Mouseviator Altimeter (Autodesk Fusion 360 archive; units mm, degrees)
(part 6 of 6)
sketch "Panel Sketch" plane through (0, -8.25, 0) normal (0, -1, 0) x axis (1, 0, 0)
  line L1 (-40.1846, 22.0238) -> (-35.5682, 33.812)
  line L2 (-40.4655, -20.5361) -> (-40.4655, 20.5361)
  line L3 (-35.5682, -33.812) -> (-40.1846, -22.0238)
  line L4 (-22.8502, -40.1861) -> (-33.2529, -36.1249)
  line L5 (21.3665, -40.4655) -> (-21.3665, -40.4655)
  line L6 (33.2529, -36.1249) -> (22.8502, -40.1861)
  line L7 (40.1846, -22.0238) -> (35.5682, -33.812)
  line L8 (40.4655, 20.5361) -> (40.4655, -20.5361)
  line L9 (35.5682, 33.812) -> (40.1846, 22.0238)
  line L10 (-24.1331, 40.4655) -> (24.1231, 40.4655)
  line L11 (26.0523, 39.9806) -> (33.1998, 36.1452)
  line L12 (-33.685, 35.9265) -> (-26.049, 39.9877)
  circle C1 centre (31.4309, 31.4309) radius 2.159
  circle C2 centre (-31.4309, -31.4309) radius 2.159
  circle C3 centre (-31.4309, 31.4309) radius 2.159
  circle C4 centre (31.4309, -31.4309) radius 2.159
  circle C5 centre (0, 0) radius 39.6875
  arc A1 centre (-36.3855, 20.5361) radius 4.08 clockwise from (-40.4655, 20.5361) to (-40.1846, 22.0238)
  arc A2 centre (-36.3855, -20.5361) radius 4.08 clockwise from (-40.1846, -22.0238) to (-40.4655, -20.5361)
  arc A3 centre (-31.7692, -32.3242) radius 4.08 clockwise from (-33.2529, -36.1249) to (-35.5682, -33.812)
  arc A4 centre (-21.3665, -36.3855) radius 4.08 clockwise from (-21.3665, -40.4655) to (-22.8502, -40.1861)
  arc A5 centre (21.3665, -36.3855) radius 4.08 clockwise from (22.8502, -40.1861) to (21.3665, -40.4655)
  arc A6 centre (31.7692, -32.3242) radius 4.08 clockwise from (35.5682, -33.812) to (33.2529, -36.1249)
  arc A7 centre (36.3855, -20.5361) radius 4.08 clockwise from (40.4655, -20.5361) to (40.1846, -22.0238)
  arc A8 centre (36.3855, 20.5361) radius 4.08 clockwise from (40.1846, 22.0238) to (40.4655, 20.5361)
  arc A9 centre (31.7692, 32.3242) radius 4.08 clockwise from (33.1998, 36.1452) to (35.5682, 33.812)
  arc A10 centre (-31.7692, 32.3242) radius 4.08 clockwise from (-35.5682, 33.812) to (-33.685, 35.9265)
  arc A11 centre (24.1231, 36.3855) radius 4.08 clockwise from (24.1231, 40.4655) to (26.0523, 39.9806)
  arc A12 centre (-24.1331, 36.3855) radius 4.08 clockwise from (-26.049, 39.9877) to (-24.1331, 40.4655)
sketch "Clamping Holes" plane through (0, -8.25, 0) normal (0, -1, 0) x axis (1, 0, 0)
  line L1 (0, 17.2297) -> (0, 0)
  line L2 (-22.2137, 0) -> (0, 0)
  circle C1 centre (-36.96, 18.76) radius 1
  circle C2 centre (36.96, 18.76) radius 1
  circle C3 centre (-36.96, -18.76) radius 1
  circle C4 centre (36.96, -18.76) radius 1
  circle C5 centre (-18.76, 36.96) radius 1
  circle C6 centre (18.76, 36.96) radius 1
  circle C7 centre (18.76, -36.96) radius 1
  circle C8 centre (-18.76, -36.96) radius 1
  point P1 (0, 0)
  point P3 (0, 0)
  point P5 (0, 0)
  point P2 (-36.96, 18.76)
  point P10 (-18.76, 36.96)
  coincident P1 P3
  vertical L1
  coincident P1 P5
  perpendicular L1 L2
  symmetric C1 L1 C2
  symmetric C1 L2 C3
  symmetric L2 C2 C4
  symmetric L1 C5 C6
  symmetric L2 C5 C8
  symmetric L2 C6 C7
  dimension "d32" diameter C1 = 2
  dimension "d33" distance P1 P2 = 18.76 (= "( 37.52 / 2 ) * 1 mm")
  dimension "d34" distance P1 P2 = 36.96 (= "( 73.92 / 2 ) * 1 mm")
  dimension "d37" diameter C5 = 2 (= "d32")
  dimension "d38" distance P1 P10 = 36.96 (= "d34")
  dimension "d39" distance P1 P10 = 18.76 (= "d33")
hole "Hole1" HoleDepth 10.25 HoleDiameter 2.8 CBDepth 2.5 CBDiameter 5
component_from_bodies "Body->Comp"
sketch "Top Sketch" plane through (0, 0, 41.4655) normal (0, 0, 1) x axis (-1, 0, 0)
  line L1 (-24.1231, 7.25) -> (24.1331, 7.25)
  line L2 (24.1331, -2) -> (-24.1231, -2)
  line L3 (-22.19, 6.25) -> (22.19, 6.25)
  line L4 (22.19, 0.25) -> (-22.19, 0.25)
  line L5 (-22.19, 3.25) -> (22.19, 3.25)
  line L6 (-24.1231, 8.25) -> (24.1331, 8.25)
  line L7 (-24.1231, -2) -> (-24.1231, 7.25)
  line L8 (24.1331, 7.25) -> (24.1331, -2)
  line L9 (22.19, 0.1) -> (-22.19, 0.1)
  line L10 (-22.19, 6.4) -> (22.19, 6.4)
  line L11 (-15.15, 0.1) -> (15.15, 0.1)
  line L12 (-15.15, 6.4) -> (-15.15, 0.1)
  line L13 (15.15, 6.4) -> (-15.15, 6.4)
  line L14 (15.15, 0.1) -> (15.15, 6.4)
  line L15 (-15.15, 6.4) -> (15.15, 0.1)
  line L16 (15.15, 6.4) -> (-15.15, 0.1)
  arc A1 centre (-22.19, 3.25) radius 3 clockwise from (-22.19, 0.25) to (-22.19, 6.25)
  arc A2 centre (22.19, 3.25) radius 3 clockwise from (22.19, 6.25) to (22.19, 0.25)
  arc A3 centre (22.19, 3.25) radius 3.15 clockwise from (22.19, 6.4) to (22.19, 0.1)
  arc A4 centre (-22.19, 3.25) radius 3.15 clockwise from (-22.19, 0.1) to (-22.19, 6.4)
  point P12 (0, 3.25)
  point P1 (0, 0)
  point P21 (15.15, 0.1)
  point P25 (0, 3.25)
  point P11 (-22.19, 3.25)
  point P10 (22.19, 3.25)
  point P23 (-15.15, 6.4)
  point P24 (15.15, 6.4)
  tangent L3 A1
  tangent A1 L4
  parallel L3 L4
  tangent L4 A2
  tangent L3 A2
  horizontal L5
  midpoint L5 P12
  vertical P1 P12
  horizontal L11
  perpendicular L11 L12
  parallel L11 L13
  parallel L12 L14
  coincident L9 P21
  coincident L15 P25
  coincident L16 P25
  coincident P12 P25
  dimension "d54" diameter A1 = 6
  dimension "d56" distance P11 L6 = 5
  dimension "d57" distance P10 P11 = 44.38
  dimension "d60" = 0.15
  dimension "d70" distance P23 P24 = 30.3
extrude "Extrude2" cut sketch "Top Sketch" profile of L3 A1 L4 A2 L9 L10 A3 A4 against normal blind 1.7
extrude "Extrude2" cut sketch "Top Sketch" profile of L3 L4 L9 L10 L11 L12 L13 L14 to an object
work_plane "WorkPlane1"
sketch "LED Angle" plane through (0, -3.25, 41.4655) normal (0, -1, 0) x axis (1, 0, 0)
  line L1 (14.8802, -5) -> (-0.0147, -1.0089)
  line L2 (50, -10.3752) -> (0, -10.3752)
  line L3 (0, 22.6624) -> (0, -10.6292)
  line L4 (-14.8802, -5) -> (-0.0147, -1.0089)
  line L5 (-24.1331, 0) -> (24.1231, 0)
  point P1 (0, 0)
  point P2 (0, -10.6292)
  point P3 (14.8802, -5)
  point P8 (-14.8802, -5)
  horizontal L2
  vertical P1 P2
  perpendicular L2 L3
  symmetric P3 L3 P8
  dimension "d104" angle L1 L2 = 15 (= "Angular Dimension-2")
  dimension "d106" distance P3 L5 = 5
pipe "Pipe2" SectionSize 6.5 SectionThickness 1.375
component_insert "Component Insert"
joint "Assemble1" alignOffsetX 0 alignOffsetY 0 alignOffsetZ -3
copy_paste "CutPaste"
work_plane "WorkPlane1"
mirror_component "MirrorComponent1"
derived_instance "DerivedInstance1"
mirror "Mirror1" mirrorStitchTolerance 0.1
extrude "Extrude1" new body sketch "Top Sketch" profile of L3 A1 L4 A2 L12 L14 against normal blind 1.7 bodies "Top LED Holder"
sketch "Top Sketch" plane through (0, 0, 41.4655) normal (0, 0, 1) x axis (-1, 0, 0)
  line L1 (-22.19, 6.25) -> (22.19, 6.25)
  line L2 (22.19, 0.25) -> (-22.19, 0.25)
  line L3 (0, 6.25) -> (0, 0.25)
  line L4 (-12.5, 6.225) -> (12.5, 6.225)
  line L5 (12.5, 0.275) -> (-12.5, 0.275)
  line L6 (-12.5, 3.25) -> (12.5, 3.25)
  line L7 (-13.6, 7.15) -> (13.6, 7.15)
  line L8 (13.6, -0.65) -> (-13.6, -0.65)
  line L9 (-13.6, 3.25) -> (13.6, 3.25)
  arc A1 centre (22.19, 3.25) radius 3 clockwise from (22.19, 6.25) to (22.19, 0.25)
  arc A2 centre (-22.19, 3.25) radius 3 clockwise from (-22.19, 0.25) to (-22.19, 6.25)
  arc A3 centre (-12.5, 3.25) radius 2.975 clockwise from (-12.5, 0.275) to (-12.5, 6.225)
  arc A4 centre (12.5, 3.25) radius 2.975 clockwise from (12.5, 6.225) to (12.5, 0.275)
  arc A5 centre (-13.6, 3.25) radius 3.9 clockwise from (-13.6, -0.65) to (-13.6, 7.15)
  arc A6 centre (13.6, 3.25) radius 3.9 clockwise from (13.6, 7.15) to (13.6, -0.65)
  circle C1 centre (-15.475, 3.25) radius 2.5
  circle C2 centre (15.475, 3.25) radius 2.5
  circle C3 centre (16.5801, 3.25) radius 1.5
  point P8 (0, 0.25)
  point P9 (0, 6.25)
  point P16 (0, 3.25)
  point P22 (-13.6, 3.25)
  point P23 (0, 3.25)
  point P24 (-15.475, 3.25)
  point P25 (15.475, 3.25)
  point P26 (16.5801, 3.25)
  midpoint L2 P8
  midpoint L1 P9
  tangent L4 A3
  tangent A3 L5
  parallel L4 L5
  tangent L5 A4
  tangent L4 A4
  perpendicular L3 L6
  midpoint L3 P16
  midpoint L6 P16
  tangent L7 A5
  tangent A5 L8
  parallel L7 L8
  tangent L8 A6
  tangent L7 A6
  coincident L6 P22
  parallel L6 L9
  coincident P16 P23
  midpoint L9 P23
  midpoint A3 P24
  midpoint A4 P25
  horizontal P23 P26
  dimension "d115" distance L4 L5 = 5.95
  dimension "d116" = 30.95
  dimension "d117" distance L7 L8 = 7.8
  dimension "d118" = 35
  dimension "d123" diameter C2 = 5
  dimension "d124" diameter C1 = 5 (= "d123")
  dimension "d126" diameter C3 = 3
extrude "Extrude2" add sketch "Top Sketch" profile of L4 A3 L5 A4 C1 C2 C3 along normal blind 2
extrude "Extrude3" add sketch "Top Sketch" profile of L1 L2 L4 A3 L5 A4 L7 A5 L8 A6 C1 C2 along normal blind 1
chamfer "Chamfer1" distance 0.8
extrude "Extrude4" cut sketch "Top Sketch" profile of A4 A6 C2 C3 to an object
sketch "Bottom Sketch" plane through (0, 0, 39.7655) normal (0, 0, -1) x axis (1, 0, 0)
  line L1 (22.19, 0.25) -> (-22.19, 0.25)
  line L2 (-22.19, 6.25) -> (22.19, 6.25)
  line L3 (9, 0.25) -> (-9, 0.25)
  line L4 (-9, 6.25) -> (9, 6.25)
  line L5 (9, 3.25) -> (-9, 3.25)
  line L6 (-11.5981, 4.75) -> (-16.5801, 4.75)
  line L7 (-11.5981, 1.75) -> (-11.5981, 4.75)
  line L8 (-16.5801, 1.75) -> (-11.5981, 1.75)
  line L9 (-16.5801, 4.75) -> (-16.5801, 1.75)
  circle C1 centre (-16.5801, 3.25) radius 1.5
  arc A1 centre (-22.19, 3.25) radius 3 clockwise from (-22.19, 0.25) to (-22.19, 6.25)
  arc A2 centre (22.19, 3.25) radius 3 clockwise from (22.19, 6.25) to (22.19, 0.25)
  circle C2 centre (-16.5801, 3.25) radius 1
  arc A3 centre (9, 3.25) radius 3 clockwise from (9, 6.25) to (9, 0.25)
  arc A4 centre (-9, 3.25) radius 3 clockwise from (-9, 0.25) to (-9, 6.25)
  point P16 (0, 3.25)
  point P19 (-11.5981, 1.75)
  point P17 (-16.5801, 4.75)
  point P20 (-16.5801, 1.75)
  point P9 (-16.5801, 3.25)
  point P1 (0, 0)
  point P15 (9, 3.25)
  concentric C1 C2
  tangent L3 A3
  tangent A3 L4
  parallel L3 L4
  tangent L4 A4
  tangent L3 A4
  parallel L1 L5
  midpoint L5 P16
  horizontal L6
  vertical L7
  horizontal L8
  vertical L9
  coincident A4 P19
  coincident C1 P17
  coincident C1 P20
  vertical P9 P20
  vertical P1 P16
  horizontal P9 P16
  dimension "d129" diameter A3 = 6
  dimension "d130" distance P15 P16 = 9
extrude "Extrude5" cut sketch "Bottom Sketch" profile of C1 L1 L2 L3 A3 L4 A4 L6 L7 L8 against normal blind 1
extrude "Extrude6" cut sketch "Bottom Sketch" profile of L1 L2 L3 A3 L4 A4 L7 against normal blind 2.5
work_plane "WorkPlane1"
hole "Hole1" HoleDepth 7 HoleDiameter 3.2 CSDiameter 6.3
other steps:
derived_base_feature "Derived Base Feature"
pipe "Pipe2" SectionSize 6.5 SectionThickness 1.375
mirror "Mirror1" mirrorStitchTolerance 0.1
base_feature "Base Feature" bodies "Standard Bezel"
extrude "Extrude1" cut sketch "Top Sketch" profile of L3 A1 L4 A2 L9 L10 A3 A4 against normal blind 1.7
pipe "Pipe2" SectionSize 6.5 SectionThickness 1.375
mirror "Mirror1" mirrorStitchTolerance 0.1
hole "Hole1" HoleDepth 7 HoleDiameter 3.2 CSDiameter 6.3
create_component "CreateComponent1"
create_component "CreateComponent2"
create_component "CreateComponent4"
remove_body "RemoveBody1"
extrude "Extrude2" cut sketch "Top Sketch" profile of L3 A1 L4 A2 L9 L10 A3 A4 against normal blind 1.7
joint_origin "JointOrigin1"
create_component "CreateComponent5"
remove_instance "RemoveInstance1"
create_component "CreateComponent1"
create_component "CreateComponent6"
named bodies: "Standard Bezel", "Seal", "Top LED Holder"

design "Bezel VSI & ALT MS33549B" references "Bezel LED and Glass MS33638C"
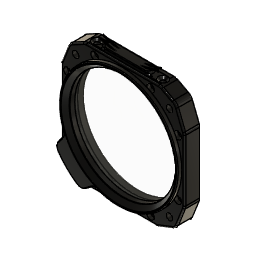
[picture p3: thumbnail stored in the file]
external_derived "ExternalDerived1" bodies "Standard Bezel"
external_derived "Top Sketch" bodies "Body1", "Body2", "Top LED Holder"
derived_instance "DerivedInstance3"
derived_instance "DerivedInstance4"
derived_instance "DerivedInstance1"
derived_instance "DerivedInstance2"
canvas "Canvas2"
sketch "Front Face" plane through (0, 2, 0) normal (0, 1, 0) x axis (-1, 0, 0)
  line L1 (28.9018, -41.4655) -> (21.3689, -41.4655)
  line L2 (41.4655, -20.5361) -> (41.4655, -28.9018)
  line L3 (31.4309, -31.4309) -> (0, 0)
  line L4 (1.8865, 0) -> (0, 0)
  line L5 (27.7621, 0) -> (1.8865, 0)
  line L6 (1.5, -41.4655) -> (1.5, -39.6216)
  line L7 (21.3665, -41.4655) -> (1.5, -41.4655)
  line L8 (33.6166, -37.0564) -> (23.2139, -41.1177)
  line L9 (41.1157, -22.3885) -> (36.4994, -34.1766)
  line L10 (41.4655, 20.5361) -> (41.4655, -20.5361)
  line L11 (36.4994, 34.1766) -> (41.1157, 22.3885)
  line L12 (26.5185, 40.8706) -> (34.1546, 36.8093)
  line L13 (-24.1231, 41.4655) -> (24.1331, 41.4655)
  line L14 (-33.6166, 37.0564) -> (-26.5251, 40.8618)
  line L15 (-41.1157, 22.3885) -> (-36.4994, 34.1766)
  line L16 (-41.4655, -20.5361) -> (-41.4655, 20.5361)
  line L17 (-36.4994, -34.1766) -> (-41.1157, -22.3885)
  line L18 (-23.2139, -41.1177) -> (-33.6166, -37.0564)
  line L19 (-1.5, -41.4655) -> (-21.3665, -41.4655)
  line L20 (-1.5, -39.6216) -> (-1.5, -41.4655)
  line L21 (11.4332, -8.6898) -> (41.4655, -8.6898)
  line L22 (11.4332, -41.4655) -> (11.4332, -8.6898)
  line L23 (41.4655, -41.4655) -> (11.4332, -41.4655)
  line L24 (41.4655, -8.6898) -> (41.4655, -41.4655)
  line L25 (1.5, -41.4655) -> (1.5, -39.6216)
  line L26 (21.3665, -41.4655) -> (1.5, -41.4655)
  line L27 (33.6166, -37.0564) -> (23.2139, -41.1177)
  line L28 (41.1157, -22.3885) -> (36.4994, -34.1766)
  line L29 (41.4655, 20.5361) -> (41.4655, -20.5361)
  line L30 (36.4994, 34.1766) -> (41.1157, 22.3885)
  line L31 (26.5185, 40.8706) -> (34.1546, 36.8093)
  line L32 (-24.1231, 41.4655) -> (24.1331, 41.4655)
  line L33 (-33.6166, 37.0564) -> (-26.5251, 40.8618)
  line L34 (-41.1157, 22.3885) -> (-36.4994, 34.1766)
  line L35 (-41.4655, -20.5361) -> (-41.4655, 20.5361)
  line L36 (-36.4994, -34.1766) -> (-41.1157, -22.3885)
  line L37 (-23.2139, -41.1177) -> (-33.6166, -37.0564)
  line L38 (-1.5, -41.4655) -> (-21.3665, -41.4655)
  line L39 (-1.5, -39.6216) -> (-1.5, -41.4655)
  arc A1 centre (28.9018, -28.9018) radius 12.5637 clockwise from (41.4655, -28.9018) to (28.9018, -41.4655)
  circle C1 centre (31.4309, -31.4309) radius 1.5
  circle C2 centre (-36.96, 18.76) radius 1
  circle C3 centre (-18.76, -36.96) radius 1
  circle C4 centre (36.96, -18.76) radius 1
  circle C5 centre (18.76, 36.96) radius 1
  circle C6 centre (36.96, 18.76) radius 1
  circle C7 centre (18.76, -36.96) radius 1
  circle C8 centre (-36.96, -18.76) radius 1
  circle C9 centre (-18.76, 36.96) radius 1
  arc A2 centre (21.3665, -36.3855) radius 5.08 clockwise from (23.2139, -41.1177) to (21.3665, -41.4655)
  arc A3 centre (31.7692, -32.3242) radius 5.08 clockwise from (36.4994, -34.1766) to (33.6166, -37.0564)
  arc A4 centre (36.3855, -20.5361) radius 5.08 clockwise from (41.4655, -20.5361) to (41.1157, -22.3885)
  arc A5 centre (36.3855, 20.5361) radius 5.08 clockwise from (41.1157, 22.3885) to (41.4655, 20.5361)
  arc A6 centre (31.7692, 32.3242) radius 5.08 clockwise from (34.1546, 36.8093) to (36.4994, 34.1766)
  arc A7 centre (24.1331, 36.3855) radius 5.08 clockwise from (24.1331, 41.4655) to (26.5185, 40.8706)
  arc A8 centre (-24.1231, 36.3855) radius 5.08 clockwise from (-26.5251, 40.8618) to (-24.1231, 41.4655)
  arc A9 centre (-31.7692, 32.3242) radius 5.08 clockwise from (-36.4994, 34.1766) to (-33.6166, 37.0564)
  arc A10 centre (-36.3855, 20.5361) radius 5.08 clockwise from (-41.4655, 20.5361) to (-41.1157, 22.3885)
  arc A11 centre (-36.3855, -20.5361) radius 5.08 clockwise from (-41.1157, -22.3885) to (-41.4655, -20.5361)
  arc A12 centre (-31.7692, -32.3242) radius 5.08 clockwise from (-33.6166, -37.0564) to (-36.4994, -34.1766)
  arc A13 centre (-21.3665, -36.3855) radius 5.08 clockwise from (-21.3665, -41.4655) to (-23.2139, -41.1177)
  arc A14 centre (0, 0) radius 39.65 clockwise from (-1.5, -39.6216) to (1.5, -39.6216)
  circle C10 centre (-31.4309, 31.4309) radius 2.159
  circle C11 centre (-31.4309, -31.4309) radius 2.159
  circle C12 centre (31.4309, 31.4309) radius 2.159
  circle C13 centre (31.4309, -31.4309) radius 2.159
  circle C14 centre (-36.96, 18.76) radius 1.4
  circle C15 centre (-18.76, -36.96) radius 1.4
  circle C16 centre (36.96, -18.76) radius 1.4
  circle C17 centre (18.76, 36.96) radius 1.4
  circle C18 centre (36.96, 18.76) radius 1.4
  circle C19 centre (18.76, -36.96) radius 1.4
  circle C20 centre (-36.96, -18.76) radius 1.4
  circle C21 centre (-18.76, 36.96) radius 1.4
  arc A15 centre (21.3665, -36.3855) radius 5.08 clockwise from (23.2139, -41.1177) to (21.3665, -41.4655)
  arc A16 centre (31.7692, -32.3242) radius 5.08 clockwise from (36.4994, -34.1766) to (33.6166, -37.0564)
  arc A17 centre (36.3855, -20.5361) radius 5.08 clockwise from (41.4655, -20.5361) to (41.1157, -22.3885)
  arc A18 centre (36.3855, 20.5361) radius 5.08 clockwise from (41.1157, 22.3885) to (41.4655, 20.5361)
  arc A19 centre (31.7692, 32.3242) radius 5.08 clockwise from (34.1546, 36.8093) to (36.4994, 34.1766)
  arc A20 centre (24.1331, 36.3855) radius 5.08 clockwise from (24.1331, 41.4655) to (26.5185, 40.8706)
  arc A21 centre (-24.1231, 36.3855) radius 5.08 clockwise from (-26.5251, 40.8618) to (-24.1231, 41.4655)
  arc A22 centre (-31.7692, 32.3242) radius 5.08 clockwise from (-36.4994, 34.1766) to (-33.6166, 37.0564)
  arc A23 centre (-36.3855, 20.5361) radius 5.08 clockwise from (-41.4655, 20.5361) to (-41.1157, 22.3885)
  arc A24 centre (-36.3855, -20.5361) radius 5.08 clockwise from (-41.1157, -22.3885) to (-41.4655, -20.5361)
  arc A25 centre (-31.7692, -32.3242) radius 5.08 clockwise from (-33.6166, -37.0564) to (-36.4994, -34.1766)
  arc A26 centre (-21.3665, -36.3855) radius 5.08 clockwise from (-21.3665, -41.4655) to (-23.2139, -41.1177)
  arc A27 centre (0, 0) radius 39.65 clockwise from (-1.5, -39.6216) to (1.5, -39.6216)
  circle C22 centre (-31.4309, 31.4309) radius 2.159
  circle C23 centre (-31.4309, -31.4309) radius 2.159
  circle C24 centre (31.4309, 31.4309) radius 2.159
  circle C25 centre (31.4309, -31.4309) radius 2.159
  point P7 (31.4309, -31.4309)
  point P11 (31.4309, -31.4309)
  point P30 (41.4655, -20.5361)
  point P68 (11.4332, -41.4655)
  point P66 (41.4655, -8.6898)
  point P65 (31.4309, -31.4309)
  point P5 (28.9018, -28.9018)
  tangent L1 A2
  tangent L1 A1
  tangent L2 A1
  horizontal L4
  parallel L4 L5
  coincident P7 P11
  vertical L2
  horizontal L1
  coincident P30
  horizontal L21
  vertical L22
  horizontal L23
  vertical L24
  midpoint L7 P68
  coincident L10 P66
  coincident P11 P65
  coincident P5 L3
  dimension "d2" angle L3 L5 = 45 (= "Angular Dimension-2")
  dimension "d5" diameter C1 = 3
extrude "Extrude1" add sketch "Front Face" profile of C4 C7 L7 A2 L8 A3 L9 A4 L10 L1 L2 A1 C1 A14 C13 L21 L22 L23 L24 to an object
sketch "Hump" plane through (0, -8.25, 0) normal (0, -1, 0) x axis (1, 0, 0)
  line L1 (-52.3265, -52.3265) -> (0, 0)
  line L2 (-31.4309, -31.4309) -> (0, 0)
  line L3 (-17.9284, -37.2375) -> (-22.1954, -40.4897)
  line L4 (-37.2375, -17.9284) -> (-40.4897, -22.1954)
  line L5 (-11.4332, -41.4655) -> (-28.9018, -41.4655)
  line L6 (-41.4655, -28.9018) -> (-41.4655, -8.6898)
  line L7 (-36.8176, -11.883) -> (-36.8176, -14.8175)
  line L8 (-3.8505, -36.8176) -> (-14.8175, -36.8176)
  line L9 (21.3665, -40.4655) -> (-11.4332, -40.4655)
  line L10 (-41.4655, -8.6898) -> (-40.4655, -8.6898)
  line L11 (-11.4332, -40.4655) -> (-11.4332, -41.4655)
  line L12 (33.2529, -36.1249) -> (22.8502, -40.1861)
  line L13 (40.1846, -22.0238) -> (35.5682, -33.812)
  line L14 (40.4655, 20.5361) -> (40.4655, -20.5361)
  line L15 (35.5682, 33.812) -> (40.1846, 22.0238)
  line L16 (26.0523, 39.9806) -> (33.1998, 36.1452)
  line L17 (-24.1331, 40.4655) -> (24.1231, 40.4655)
  line L18 (-33.685, 35.9265) -> (-26.049, 39.9877)
  line L19 (-40.1846, 22.0238) -> (-35.5682, 33.812)
  line L20 (-40.4655, -8.6898) -> (-40.4655, 20.5361)
  arc A1 centre (0, 0) radius 49.2252 clockwise from (-27.7854, -40.6336) to (-34.8075, -34.8075)
  arc A2 centre (-16.0038, -39.7627) radius 3.175 clockwise from (-17.9284, -37.2375) to (-14.8175, -36.8176)
  arc A3 centre (-25.09, -36.6919) radius 4.7752 clockwise from (-22.1954, -40.4897) to (-27.7854, -40.6336)
  circle C1 centre (0, 0) radius 39.6875
  arc A4 centre (-39.7627, -16.0038) radius 3.175 clockwise from (-36.8176, -14.8175) to (-37.2375, -17.9284)
  arc A5 centre (-36.6919, -25.09) radius 4.7752 clockwise from (-40.6336, -27.7854) to (-40.4897, -22.1954)
  arc A6 centre (0, 0) radius 49.2252 clockwise from (-34.8075, -34.8075) to (-40.6336, -27.7854)
  arc A7 centre (-28.9018, -28.9018) radius 12.5637 clockwise from (-28.9018, -41.4655) to (-41.4655, -28.9018)
  circle C2 centre (0, 0) radius 38.6878
  circle C3 centre (31.4309, 31.4309) radius 2.159
  circle C4 centre (31.4309, -31.4309) radius 2.159
  circle C5 centre (-31.4309, 31.4309) radius 2.159
  arc A8 centre (21.3665, -36.3855) radius 4.08 clockwise from (22.8502, -40.1861) to (21.3665, -40.4655)
  arc A9 centre (31.7692, -32.3242) radius 4.08 clockwise from (35.5682, -33.812) to (33.2529, -36.1249)
  arc A10 centre (36.3855, -20.5361) radius 4.08 clockwise from (40.4655, -20.5361) to (40.1846, -22.0238)
  arc A11 centre (36.3855, 20.5361) radius 4.08 clockwise from (40.1846, 22.0238) to (40.4655, 20.5361)
  arc A12 centre (31.7692, 32.3242) radius 4.08 clockwise from (33.1998, 36.1452) to (35.5682, 33.812)
  arc A13 centre (24.1231, 36.3855) radius 4.08 clockwise from (24.1231, 40.4655) to (26.0523, 39.9806)
  arc A14 centre (-24.1331, 36.3855) radius 4.08 clockwise from (-26.049, 39.9877) to (-24.1331, 40.4655)
  arc A15 centre (-31.7692, 32.3242) radius 4.08 clockwise from (-35.5682, 33.812) to (-33.685, 35.9265)
  arc A16 centre (-36.3855, 20.5361) radius 4.08 clockwise from (-40.4655, 20.5361) to (-40.1846, 22.0238)
  arc A17 centre (0, 0) radius 39.6875 clockwise from (16.3978, -36.1415) to (-36.1415, 16.3978)
  arc A18 centre (-36.96, 18.76) radius 2.5 clockwise from (-36.1415, 16.3978) to (-34.5701, 19.4937)
  arc A19 centre (0, 0) radius 39.6875 clockwise from (-34.5701, 19.4937) to (-19.4937, 34.5701)
  arc A20 centre (-18.76, 36.96) radius 2.5 clockwise from (-19.4937, 34.5701) to (-16.3978, 36.1415)
  arc A21 centre (0, 0) radius 39.6875 clockwise from (-16.3978, 36.1415) to (16.3978, 36.1415)
  arc A22 centre (18.76, 36.96) radius 2.5 clockwise from (16.3978, 36.1415) to (19.4937, 34.5701)
  arc A23 centre (0, 0) radius 39.6875 clockwise from (19.4937, 34.5701) to (34.5701, 19.4937)
  arc A24 centre (36.96, 18.76) radius 2.5 clockwise from (34.5701, 19.4937) to (36.1415, 16.3978)
  arc A25 centre (0, 0) radius 39.6875 clockwise from (36.1415, 16.3978) to (36.1415, -16.3978)
  arc A26 centre (36.96, -18.76) radius 2.5 clockwise from (36.1415, -16.3978) to (34.5701, -19.4937)
  arc A27 centre (0, 0) radius 39.6875 clockwise from (34.5701, -19.4937) to (19.4937, -34.5701)
  arc A28 centre (18.76, -36.96) radius 2.5 clockwise from (19.4937, -34.5701) to (16.3978, -36.1415)
  point P1 (0, 0)
  point P2 (0, 0)
  point P5 (0, 0)
  point P3 (-34.8075, -34.8075)
  point P10 (-14.8175, -36.8176)
  point P15 (-24.9671, -41.4655)
  point P23 (-34.8075, -34.8075)
  point P4 (-27.7854, -40.6336)
  point P21 (-40.6336, -27.7854)
  point P17 (-36.8176, -14.8175)
  point P11 (-17.9284, -37.2375)
  point P18 (-37.2375, -17.9284)
  point P13 (-22.1954, -40.4897)
  point P19 (-40.4897, -22.1954)
  point P30 (0, 0)
  coincident P1 P2
  coincident P1 P5
  collinear L1 L2
  coincident P3 L1
  coincident P10 C1
  tangent A2 L3
  tangent A3 L3
  tangent A1 A3
  midpoint A3 P15
  symmetric P3 L1 P23
  symmetric P4 L1 P21
  symmetric A1 L1 A6
  symmetric L1 P10 P17
  symmetric L1 P11 P18
  symmetric L1 A2 A4
  symmetric L1 P13 P19
  symmetric L1 A3 A5
  vertical L7
  horizontal L8
  coincident P1 P30
  dimension "d8" radius A1 = 49.2252 (= "1.938")
  dimension "d9" radius A2 = 3.175 (= "0.125")
  dimension "d12" radius A3 = 4.7752 (= "0.188")
extrude "Extrude2" add sketch "Hump" profile of A1 L2 A2 A3 C1 L3 A4 L4 A5 A6 L5 L6 C2 L7 L8 A17 to an object
extrude "Extrude3" new body sketch "Hump" profile of A1 L2 A2 A3 C1 L3 A4 L4 A5 A6 L6 L9 C2 L7 L8 to an object bodies "ALT VSI Bezel"
external_derived "Sketch1" bodies "Body1", "Seal"
derived_instance "DerivedInstance1"
derived_instance "DerivedInstance2"
combine "Combine1" bodies "Standard Bezel"
fillet "Fillet1" radius 1.27 (= "0.05") 0.508 (= "0.02")
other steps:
derived_base_feature "Derived Base Feature1"
derived_base_feature "Derived Base Feature1" bodies "Body1", "Body2"
derived_base_feature "Top Sketch" bodies "Top LED Holder"
derived_base_feature "Derived Base Feature1" bodies "Body1", "Body2"
derived_base_feature "Sketch1" bodies "Seal"
derived_base_feature "Sketch1" bodies "Body1"
derived_base_feature "Derived Base Feature2" bodies "Standard Bezel"
create_component "CreateComponent1"
create_component "CreateComponent2"
create_component "CreateComponent3"
create_component "CreateComponent4"
create_component "CreateComponent5"
create_component "CreateComponent6"
named bodies: "Body1", "Standard Bezel", "ALT VSI Bezel", "Seal", "Body2", "Top LED Holder"

design "ULN2003 Stepper Driver v18"
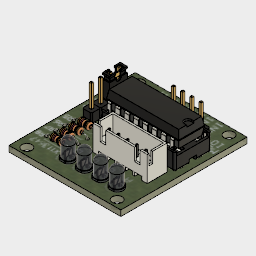
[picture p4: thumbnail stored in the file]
parameter "dip16_package_length" = 20
parameter "dip16_package_width" = 7.1
parameter "dip16_package_height" = 4.6
parameter "dip16_above_board" = 0.51
parameter "dip16_lead_thick" = 0.25
parameter "dip16_lead_width" = 1.35 comment "1.14 - 1.65"
parameter "dip16_lead_spacing" = 2.54
parameter "dip16_lead_extension" = 0.26
parameter "dip16_package_taper" = 10
parameter "dip16_lead_foot_length" = 3.3 comment "0.41 - 0.89"
parameter "dip16_lead_foot_angle" = 1 comment "0 - 8"
parameter "dip16_lead_upper_length" = 2.685 (= "dip16_above_board + ( dip16_package_height - dip16_lead_thick ) / 2")
parameter "dip16_lead_foot_width" = 0.45 comment "0.36 - 0.66"
parameter "dip16_socket_length" = 20.32 comment "tol + 0 - 0.05 mm"
parameter "dip16_socket_width" = 10.04 (= "0.4 in - 0.12 mm") comment "tol + 0.1 - 0.05 mm"
parameter "dip16_socket_height" = 5.04
parameter "dip16_socket_lead_thick" = 0.16
parameter "dip16_socket_lead_width" = 1.25
parameter "dip16_socket_lead_foot_width" = 0.62
parameter "dip16_socket_lead_length" = 8.2
parameter "dip16_socket_above_board" = 0.25
parameter "dip16_socket_lead_spacing" = 2.54
parameter "dip16_socket_length_1" = 20.32 comment "tol + 0 - 0.05 mm"
parameter "dip16_socket_width_1" = 10.04 (= "0.4 in - 0.12 mm") comment "tol + 0.1 - 0.05 mm"
parameter "dip16_socket_height_1" = 5.04
parameter "dip16_socket_lead_thick_1" = 0.16
parameter "dip16_socket_lead_width_1" = 1.25
parameter "dip16_socket_lead_foot_width_1" = 0.62
parameter "dip16_socket_lead_length_1" = 8.2
parameter "dip16_socket_above_board_1" = 0.25
parameter "dip16_socket_lead_spacing_1" = 2.54
base_feature "Base Feature1"
base_feature "Base Feature1"
base_feature "Base Feature1"
extrude "Extrude1" sketch "unnamed" blind 2.54
sketch "Sketch1"
  dimension "d5" = 0.635
extrude "Extrude2" sketch "Sketch1" blind -2.54
sketch "Sketch1"
  dimension "d8_1" = 0.635
  dimension "d9_2" = 0.635
extrude "Extrude1" sketch "Sketch1" blind 8.89 named "d10_2" second side blind 2.54 named "d12_2"
chamfer "Chamfer1" distance 0.1588 named "d13_2"
copy_paste "CutPaste1"
copy_paste "CutPaste2"
rectangular_pattern "R-Pattern1" uSpaceDistance 2.54 named "d16_2" vSpaceDistance 2.54 named "d17_2"
base_feature "Base Feature1"
extrude "Extrude1" sketch "unnamed" blind 2.54 named "d1_1"
sketch "Sketch1"
  dimension "d5_1" = 0.635
extrude "Extrude2" sketch "Sketch1" blind -2.54 named "d6_1"
sketch "Sketch1"
  dimension "d8_2" = 0.635
  dimension "d9_3" = 0.635
extrude "Extrude1" sketch "Sketch1" blind 8.89 named "d10_3" second side blind 2.54 named "d12_3"
chamfer "Chamfer1" distance 0.1588 named "d13_3"
copy_paste "CutPaste1"
copy_paste "CutPaste2"
rectangular_pattern "R-Pattern1" countU 4 (= "pins_wide_1") named "d14_3" uSpaceDistance 2.54 named "d16_3" vSpaceDistance 2.54 named "d17_3"
base_feature "Base Feature1"
position "Position1"
copy_paste "CopyPaste1"
copy_paste "CopyPaste2"
copy_paste "CopyPaste3"
work_plane "WorkPlane1" AlongDistance 2.81 (= "dip16_above_board + dip16_package_height / 2")
sketch "Sketch1"
  dimension "d13" = 7.1 (= "dip16_package_width")
  dimension "d14" = 20 (= "dip16_package_length")
extrude "Extrude1" sketch "Sketch1" blind -0.125 (= "-dip16_lead_thick / 2")
sketch "Sketch2"
extrude "Extrude2" sketch "Sketch2" blind 2.175 (= "( dip16_package_height - dip16_lead_thick ) / 2") taper -10 (= "-dip16_package_taper")
mirror "Mirror1"
combine "Combine1"
work_plane "WorkPlane1" AlongDistance -1.27 (= "-dip16_lead_spacing / 2")
sketch "Sketch1"
  dimension "d23" = 0.08
  dimension "d24" = 2.685 (= "dip16_above_board + ( dip16_package_height - dip16_lead_thick ) / 2")
  dimension "d28" = 0.15
  dimension "d29" = 3.55 (= "dip16_package_width / 2")
  dimension "d53" = 91 (= "90 deg + dip16_lead_foot_angle")
  dimension "d55" = 0.26 (= "dip16_lead_extension")
  dimension "d56" = 0.25 (= "dip16_lead_thick")
  dimension "d57" = 0.43 (= "dip16_above_board - d23")
extrude "Extrude1" sketch "Sketch1" blind 0.675 (= "dip16_lead_width / 2")
sketch "Sketch2"
  dimension "d58" = 45
  dimension "d59" = 2.175 (= "dip16_lead_upper_length - dip16_above_board")
  dimension "d60" = 3.3 (= "dip16_lead_foot_length")
  dimension "d61" = 0.45 (= "dip16_lead_foot_width")
extrude "Extrude2" sketch "Sketch2" blind -0.25 (= "-dip16_lead_thick")
extrude "Extrude3" sketch "Sketch2" blind 0.125 (= "dip16_lead_thick / 2")
fillet "Fillet1" radius 0.05
rectangular_pattern "R-Pattern1" uSpaceDistance 2.54 (= "dip16_lead_spacing") vSpaceDistance 0
mirror "Mirror1"
sketch "Sketch3"
  dimension "d74" = 2
  dimension "d75" = 1
extrude "Extrude3" sketch "Sketch3" blind -0.5 taper -5
sketch "Sketch2 (1)"
  dimension "d67" = 10 (= "dip16_package_length / 2")
  dimension "d68" = 0.82 (= "( dip16_lead_spacing ) / 2 - dip16_lead_foot_width")
  dimension "d69" = 5.11 (= "dip16_above_board + dip16_package_height")
  dimension "d70" = 3.3 (= "dip16_lead_foot_length")
extrude "Extrude4" sketch "Sketch2 (1)" no distance stored
base_feature "Base Feature1"
copy_paste "CopyPaste1"
copy_paste "CopyPaste2"
copy_paste "CopyPaste3"
copy_paste "CopyPaste4"
sketch "Sketch1"
  dimension "d7" = 31
  dimension "d8" = 35
  dimension "d9" = 2.75
  dimension "d10" = 3
  dimension "d11" = 2
  dimension "d22" = 25 (= "d7 - 2 * d10")
  dimension "d25" = -31 (= "-d8 + 2 * d11")
extrude "Extrude1" sketch "Sketch1" blind 1.6
sketch "Sketch2"
  dimension "d30" = 0.8
  dimension "d36" = -2.54
  dimension "d37" = 7.62
  dimension "d38" = 2.54
  dimension "d39" = 10
  dimension "d40" = 0.8
  dimension "d41" = 6.5
  dimension "d42" = 9.5
  dimension "d45" = -2.54
  dimension "d46" = 0
  dimension "d52" = 0.8
  dimension "d54" = 5
  dimension "d62" = 9.5
  dimension "d80" = 0
  dimension "d81" = 2.54
  dimension "d82" = 0.8
  dimension "d83" = 3
  dimension "d84" = 20
  dimension "d87" = -6.35
  dimension "d88" = 2.54
  dimension "d89" = 0.8
  dimension "d92" = -2.54
  dimension "d93" = 0
  dimension "d94" = 5
  dimension "d95" = 12
  dimension "d96" = 0.8
  dimension "d99" = -4.445
  dimension "d100" = 1.75
  dimension "d101" = 4
  dimension "d102" = 6
extrude "Extrude2" sketch "Sketch2" blind -2
chamfer "Chamfer1" distance 0.1
position "Position2"
sketch "Sketch1"
  dimension "d106" = 0.5
  dimension "d107" = 1
  dimension "d108" = 2
  dimension "d116" = 1
work_plane "WorkPlane3"
sketch "Sketch2"
  circle C1 centre (0, -2.5) radius 0.1
  dimension "d113" diameter C1 = 0.2
sweep "Sweep1" sketch "Sketch2"
work_plane "WorkPlane2" AlongDistance 6
work_plane "WorkPlane1"
mirror "Mirror1"
position "Position3"
sketch "Sketch1"
  dimension "d9_1" = 2.51 (= "dip16_socket_width_1 * 0.25")
  dimension "d10_1" = 1
  dimension "d11_1" = 19.32 (= "dip16_socket_length_1 - 1 mm")
extrude "Extrude1" sketch "Sketch1" blind 0.25 (= "dip16_socket_above_board_1") named "d12_1"
sketch "Sketch2"
  dimension "d14_1" = 20.32 (= "dip16_socket_length_1")
  dimension "d15_1" = 10.04 (= "dip16_socket_width_1")
extrude "Extrude2" sketch "Sketch2" blind 4.79 (= "dip16_socket_height_1 - dip16_socket_above_board_1") named "d16_1" taper 1 named "d17_1"
fillet "Fillet1" radius 0.5 named "d18_1"
sketch "Sketch3"
  dimension "d20_1" = 4
  dimension "d21_1" = 0.33
  dimension "d22_1" = 2.54
  dimension "d23_1" = 1.7
  dimension "d24_1" = 3.54 (= "0.1 in + 1 mm")
extrude "Extrude3" sketch "Sketch3" blind 1.5 named "d25_1"
extrude "Extrude4" sketch "Sketch3" blind 5.04 (= "dip16_socket_height_1") named "d27_1"
sketch "Sketch4"
  dimension "d29_1" = 9.04 (= "dip16_socket_width_1 - 1 mm")
  dimension "d30_1" = 1
  dimension "d31_1" = 5.04 (= "dip16_socket_height_1")
extrude "Extrude5" sketch "Sketch4" no distance stored
work_plane "WorkPlane1"
sketch "Sketch5"
  dimension "d33_1" = 5.04 (= "dip16_socket_height_1")
  dimension "d34_1" = 0.5
  dimension "d35_1" = 2.25
  dimension "d36_1" = 4.645 (= "( dip16_socket_width_1 - 0.75 mm ) / 2")
  dimension "d37_1" = 4.395 (= "( dip16_socket_width_1 - 1.25 mm ) / 2")
  dimension "d38_1" = 0.75 (= "dip16_socket_above_board_1 + 0.5 mm")
  dimension "d39_1" = 45
  dimension "d40_1" = 45
  dimension "d41_1" = 0.16 (= "dip16_socket_lead_thick_1")
  dimension "d42_1" = 0.25 (= "dip16_socket_above_board_1")
  dimension "d44_1" = 3
extrude "Extrude6" sketch "Sketch5" blind 1.25 (= "dip16_socket_lead_width_1") named "d45_1"
rectangular_pattern "R-Pattern1" countU 8 (= "dip16_num_leads_1 / 2") named "d50_1" uSpaceDistance -2.54 named "d52_1" vSpaceDistance 0 named "d53_1"
mirror "Mirror1"
work_plane "WorkPlane1" AlongDistance 8.89 (= "( ( dip16_num_leads_1 / 2 - 1 ) * dip16_socket_lead_spacing_1 ) / 2") named "d55_1"
sketch "Sketch1"
  dimension "d56_1" = 4.54 (= "dip16_socket_height_1 - 0.5 mm")
  dimension "d57_1" = 4.62 (= "dip16_socket_width_1 / 2 - 0.4 mm")
  dimension "d58_1" = 1.75
  dimension "d59_1" = 0.25
  dimension "d61_1" = 2.6667
  dimension "d62_1" = 0.76 (= "dip16_socket_above_board_1 + 0.51 mm")
  dimension "d63_1" = 0.5
  dimension "d64_1" = 0.67
  dimension "d65_1" = 97
  dimension "d66_1" = 1
  dimension "d67_1" = 0.5
  dimension "d68_1" = 0.16
  dimension "d71_1" = 0.16 (= "dip16_socket_lead_thick_1")
  dimension "d72_1" = 0.725
  dimension "d73_1" = 0.25
  dimension "d74_1" = 3.16 (= "dip16_socket_lead_length_1 - dip16_socket_height_1")
extrude "Extrude1" sketch "Sketch1" blind 0.625 (= "dip16_socket_lead_width_1 / 2") named "d69_1"
extrude "Extrude2" sketch "Sketch1" blind 0.31 (= "dip16_socket_lead_foot_width_1 / 2") named "d75_1"
sketch "Sketch2"
  dimension "d85_1" = 60
extrude "Extrude3" sketch "Sketch2" no distance stored
rectangular_pattern "R-Pattern1" countU 8 (= "dip16_num_leads_1 / 2") named "d77_1" uSpaceDistance -2.54 (= "-dip16_socket_lead_spacing_1") named "d79_1" vSpaceDistance 0 named "d80_1"
mirror "Mirror1"
sketch "Sketch1"
  circle C1 centre (10.16, 0) radius 0.625
  dimension "d82_1" diameter C1 = 1.25
  dimension "d83_1" distance = 10.16 (= "dip16_socket_length_1 / 2")
extrude "Extrude7" sketch "Sketch1" no distance stored
position "Position4"
work_plane "WorkPlane4" AlongDistance 2.5
sketch "Sketch3"
  dimension "d119" = 6
  dimension "d120" = 10
  dimension "d121" = 0.1
  dimension "d122" = 0.2
  dimension "d124" = 0.2
  dimension "d125" = 0.4
  dimension "d126" = 1.6
  dimension "d128" = 0.9
  dimension "d129" = 0.7
  dimension "d131" = 0.25
  dimension "d132" = 0.7
  dimension "d134" = 0.3
  dimension "d135" = 0.3
revolve "Revolve1" sketch "Sketch3" AlongAngle 360
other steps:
create_component "CreateComponent1"
create_component "CreateComponent4"
create_component "CreateComponent6"
create_component "CreateComponent7"
create_component "CreateComponent10"
create_component "CreateComponent1"
create_component "CreateComponent2"
create_component "CreateComponent11"
create_component "CreateComponent1"
create_component "CreateComponent1"
create_component "CreateComponent2"
create_component "CreateComponent3"
remove_instance "RemoveInstance1"
remove_instance "RemoveInstance2"
create_component "CreateComponent13"
create_component "CreateComponent1"
create_component "CreateComponent2"
create_component "CreateComponent3"
remove_instance "RemoveInstance1"
remove_instance "RemoveInstance2"
create_component "CreateComponent14"
create_component "CreateComponent1"
create_component "CreateComponent2"
create_component "CreateComponent15"

design "LED D5 - White-Clear"
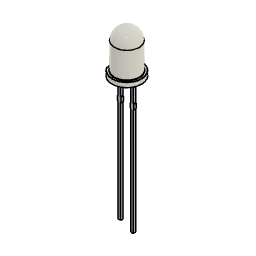
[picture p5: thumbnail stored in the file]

design "28BYJ-48"
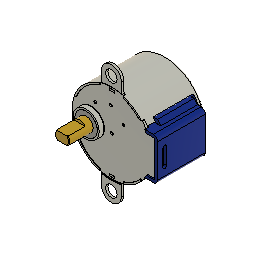
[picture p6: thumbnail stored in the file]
